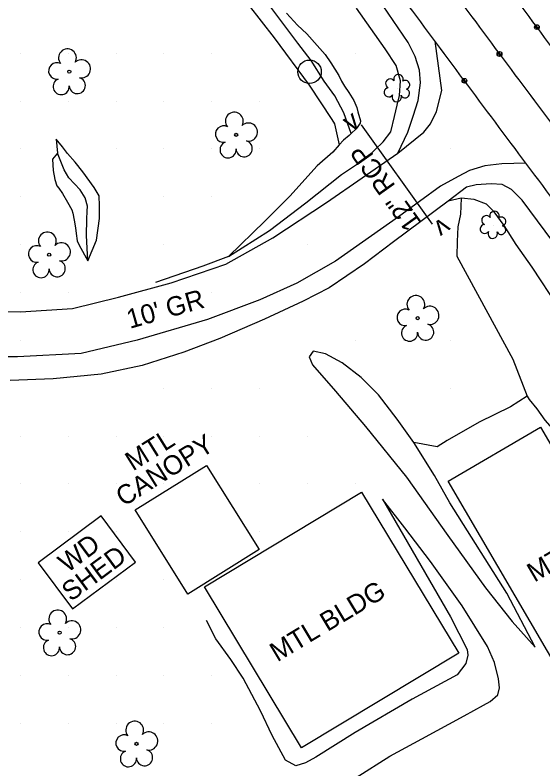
# Model space of a CAD drawing. Extents: x 1548934 to 1561348, y 809680 to 824075.
# Drawn here: x 1552078.9 to 1552189.3, y 809960.4 to 810117.9 of the extents above; entities that cross this region are included whole.
import ezdxf

# ---------------------------------------------------------------- set-up
doc = ezdxf.new("R2010")
doc.units = 0
for name, color, linetype in [('Default', 7, 'Continuous'), ('E_NCDOT_Vertical_Profile_Ground_Line', 7, 'Continuous'), ('Exist Building', 7, 'Continuous'), ('Exist Building Foundations Text', 7, 'Continuous'), ('Exist Building Metal Canopy', 7, 'Continuous'), ('Exist Building Metal Canopy Text', 7, 'Continuous'), ('Exist DTM QL2 LIDAR Elevation Point', 7, 'Continuous'), ('Exist Roads Soil', 7, 'Continuous'), ('Exist Roads Soil Text', 7, 'Continuous'), ('Exist Structure Minor Culvert Topo', 7, 'Continuous'), ('Exist Structure Minor Culvert Topo Terminator', 7, 'Continuous'), ('Exist Structure Minor Pipes RCP 12 Inch Text', 7, 'Continuous'), ('Exist Utilities Other Pole CELL', 7, 'Continuous'), ('Exist Vegetation Shrub CELL', 7, 'Continuous'), ('Exist Vegetation Tree CELL', 7, 'Continuous'), ('P_NCDOT_Vertical_Profile_Grade_Minor_Road', 7, 'Continuous'), ('PH Exist DTM Breakline', 7, 'Continuous')]:
    doc.layers.add(name, color=color, linetype=linetype)

# ---------------------------------------------------------------- blocks, each defined once
blk = doc.blocks.new('SurveyPointCell')
at = {"layer": 'Default'}
for p, q in [((-0.5, 0), (0.5, 0)), ((0, -0.5), (0, 0.5))]:
    blk.add_line(p, q, dxfattribs=at)
blk.add_circle((0, 0), 0.5, dxfattribs=at)

msp = doc.modelspace()

# ---------------------------------------------------------------- linework, layer by layer
at = {"layer": 'E_NCDOT_Vertical_Profile_Ground_Line'}
for points in [[(1552269.12, 810011.85), (1552259.92, 810023.16), (1552240.77, 810045.39), (1552214.34, 810080.42), (1552187.87, 810115.32), (1552162.13, 810150.99), (1552135.64, 810187.58), (1552109.72, 810225.45), (1552084.15, 810264.06), (1552058.91, 810303.06), (1552035.06, 810342.6), (1552011.64, 810381.93), (1551989.04, 810421.64), (1551966.75, 810462.54), (1551944.7, 810504.81), (1551922.38, 810547.42), (1551904.22, 810585.98), (1551891.94, 810609.51), (1551888.01, 810619.12)], [(1552253.41, 809998.89), (1552244.07, 810010.35), (1552226, 810034.01), (1552199.08, 810069.05), (1552172.73, 810104.35), (1552146.5, 810139.67), (1552120.17, 810176.34), (1552094.24, 810214.53), (1552068.08, 810253.47), (1552042.84, 810293.18), (1552018.16, 810332.72), (1551995.31, 810372.57), (1551972.35, 810412.52), (1551950.07, 810453.78), (1551927.46, 810496.24), (1551905.62, 810539.48), (1551886.94, 810576.33), (1551876.35, 810599.17), (1551872.14, 810607.03)]]:
    msp.add_open_spline(points, degree=3, dxfattribs=at)
at = {"layer": 'Exist Building'}
for points in [[(1552200.63, 809967.19), (1552169.44, 810020.48), (1552188.74, 810031.78), (1552219.93, 809978.48)], [(1552151.36, 810018.23), (1552171.66, 809984.55), (1552138.81, 809964.75), (1552118.5, 809998.42)], [(1552104.08, 810003.58), (1552096.93, 810013.24), (1552083.72, 810003.45), (1552090.88, 809993.8)]]:
    msp.add_lwpolyline(points, close=True, dxfattribs=at)
at = {"layer": 'Exist Building Metal Canopy'}
msp.add_lwpolyline([(1552115.03, 809996.9), (1552104.01, 810014.49), (1552118.9, 810023.82), (1552129.92, 810006.23)], close=True, dxfattribs=at)
at = {"layer": 'Exist DTM QL2 LIDAR Elevation Point'}
for p, q in [((1552080.03, 810109.94), (1552080.03, 810109.94)), ((1552090.03, 810109.94), (1552090.03, 810109.94)), ((1552100.03, 810109.94), (1552100.03, 810109.94)), ((1552110.03, 810109.94), (1552110.03, 810109.94)), ((1552120.03, 810109.94), (1552120.03, 810109.94)), ((1552150.03, 810109.94), (1552150.03, 810109.94)), ((1552080.03, 810099.94), (1552080.03, 810099.94)), ((1552090.03, 810099.94), (1552090.03, 810099.94)), ((1552100.03, 810099.94), (1552100.03, 810099.94)), ((1552110.03, 810099.94), (1552110.03, 810099.94)), ((1552120.03, 810099.94), (1552120.03, 810099.94)), ((1552130.03, 810099.94), (1552130.03, 810099.94)), ((1552080.03, 810089.94), (1552080.03, 810089.94)), ((1552100.03, 810089.94), (1552100.03, 810089.94)), ((1552110.03, 810089.94), (1552110.03, 810089.94)), ((1552120.03, 810089.94), (1552120.03, 810089.94)), ((1552130.03, 810089.94), (1552130.03, 810089.94)), ((1552170.03, 810089.94), (1552170.03, 810089.94)), ((1552080.03, 810079.94), (1552080.03, 810079.94)), ((1552110.03, 810079.94), (1552110.03, 810079.94)), ((1552120.03, 810079.94), (1552120.03, 810079.94)), ((1552080.03, 810069.94), (1552080.03, 810069.94)), ((1552110.03, 810069.94), (1552110.03, 810069.94)), ((1552140.03, 810069.94), (1552140.03, 810069.94)), ((1552080.03, 810059.94), (1552080.03, 810059.94)), ((1552090.03, 810059.94), (1552090.03, 810059.94)), ((1552120.03, 810059.94), (1552120.03, 810059.94)), ((1552080.03, 810049.94), (1552080.03, 810049.94)), ((1552150.03, 810049.94), (1552150.03, 810049.94)), ((1552160.03, 810049.94), (1552160.03, 810049.94)), ((1552170.03, 810049.94), (1552170.03, 810049.94)), ((1552110.03, 810039.93), (1552110.03, 810039.93)), ((1552120.03, 810039.93), (1552120.03, 810039.93)), ((1552130.03, 810039.93), (1552130.03, 810039.93)), ((1552170.03, 810039.93), (1552170.03, 810039.93)), ((1552080.03, 810029.93), (1552080.03, 810029.93)), ((1552090.03, 810029.93), (1552090.03, 810029.93)), ((1552100.03, 810029.93), (1552100.03, 810029.93)), ((1552110.03, 810029.93), (1552110.03, 810029.93)), ((1552120.03, 810029.93), (1552120.03, 810029.93)), ((1552130.03, 810029.93), (1552130.03, 810029.93)), ((1552140.03, 810029.93), (1552140.03, 810029.93)), ((1552080.03, 810019.93), (1552080.03, 810019.93)), ((1552090.03, 810019.93), (1552090.03, 810019.93)), ((1552100.03, 810019.93), (1552100.03, 810019.93)), ((1552110.03, 810019.93), (1552110.03, 810019.93)), ((1552130.03, 810019.93), (1552130.03, 810019.93)), ((1552140.03, 810019.93), (1552140.03, 810019.93)), ((1552150.03, 810019.93), (1552150.03, 810019.93)), ((1552080.03, 810009.93), (1552080.03, 810009.93)), ((1552090.03, 810009.93), (1552090.03, 810009.93)), ((1552100.03, 810009.93), (1552100.03, 810009.93)), ((1552130.03, 810009.93), (1552130.03, 810009.93)), ((1552080.03, 809999.93), (1552080.03, 809999.93)), ((1552100.03, 809999.93), (1552100.03, 809999.93)), ((1552110.03, 809999.93), (1552110.03, 809999.93)), ((1552120.03, 809999.93), (1552120.03, 809999.93)), ((1552080.03, 809989.93), (1552080.03, 809989.93)), ((1552090.03, 809989.93), (1552090.03, 809989.93)), ((1552100.03, 809989.93), (1552100.03, 809989.93)), ((1552110.03, 809989.93), (1552110.03, 809989.93)), ((1552080.03, 809979.93), (1552080.03, 809979.93)), ((1552090.03, 809979.93), (1552090.03, 809979.93)), ((1552100.03, 809979.93), (1552100.03, 809979.93)), ((1552110.03, 809979.93), (1552110.03, 809979.93)), ((1552120.03, 809979.93), (1552120.03, 809979.93)), ((1552080.03, 809969.93), (1552080.03, 809969.93)), ((1552090.03, 809969.93), (1552090.03, 809969.93)), ((1552100.03, 809969.93), (1552100.03, 809969.93)), ((1552110.03, 809969.93), (1552110.03, 809969.93)), ((1552120.03, 809969.93), (1552120.03, 809969.93))]:
    msp.add_line(p, q, dxfattribs=at)
at = {"layer": 'Exist Roads Soil'}
for points in [[(1552044.96, 810063.14), (1552052.35, 810059.76), (1552062.2, 810057.09), (1552070.88, 810056.03), (1552080.06, 810055.92), (1552090.93, 810056.58), (1552100.5, 810058.98), (1552111.54, 810061.99), (1552122.94, 810065.88), (1552132.77, 810071.34), (1552144.02, 810078.74), (1552158.97, 810089.08), (1552164.36, 810093.46), (1552165.76, 810095.23), (1552167.04, 810097.8), (1552168.11, 810102.17), (1552166.72, 810112.47)], [(1552185.73, 810086.96), (1552180.66, 810086.85), (1552177.16, 810086.45), (1552173.95, 810085.47), (1552171.53, 810084.19), (1552167.84, 810082.19), (1552159.11, 810075.77), (1552145.91, 810066.49), (1552137.8, 810061.9), (1552130.07, 810058.38), (1552119.16, 810054.32), (1552104.43, 810049.99), (1552092.73, 810047.17), (1552079.42, 810046.49), (1552071.79, 810046.48), (1552062.54, 810047.25), (1552052.29, 810048.42), (1552044.39, 810051.11), (1552038.17, 810053.8), (1552035.61, 810056.33)]]:
    msp.add_lwpolyline(points, dxfattribs=at)
at = {"layer": 'Exist Structure Minor Culvert Topo'}
msp.add_line((1552151.26, 810095.02), (1552166.12, 810074.23), dxfattribs=at)
at = {"layer": 'Exist Utilities Other Pole CELL'}
msp.add_circle((1552140.48, 810106.08), 2.46, dxfattribs=at)
at = {"layer": 'Exist Vegetation Shrub CELL'}
for p, q in [((1552158.83, 810102.49), (1552158.83, 810102.49)), ((1552178.91, 810073.92), (1552178.91, 810073.92))]:
    msp.add_line(p, q, dxfattribs=at)
for centre, radius, start, end in [((1552159.06, 810104.53), 0.99, 334.8391, 200.4717), ((1552157.35, 810103.61), 0.968, 35.8908, 245.4216), ((1552160.5, 810103.36), 0.929, 284.4567, 126.0861), ((1552157.03, 810101.78), 0.955, 95.1099, 327.9534), ((1552160.47, 810101.56), 0.937, 204.9913, 73.4601), ((1552158.7, 810100.8), 0.984, 151.2797, 21.387), ((1552179.14, 810075.96), 0.99, 334.8391, 200.4717), ((1552177.43, 810075.05), 0.968, 35.8908, 245.4216), ((1552180.58, 810074.79), 0.929, 284.4567, 126.0861), ((1552177.11, 810073.22), 0.955, 95.1099, 327.9534), ((1552180.55, 810073), 0.937, 204.9913, 73.4601), ((1552178.78, 810072.24), 0.984, 151.2797, 21.387)]:
    msp.add_arc(centre, radius, start, end, dxfattribs=at)
at = {"layer": 'Exist Vegetation Tree CELL'}
for p, q in [((1552090.25, 810106.11), (1552090.25, 810106.11)), ((1552125.14, 810092.89), (1552125.14, 810092.89)), ((1552086.04, 810067.84), (1552086.04, 810067.84)), ((1552163.09, 810054.58), (1552163.09, 810054.58)), ((1552088.21, 809988.84), (1552088.21, 809988.84)), ((1552104.3, 809965.62), (1552104.3, 809965.62))]:
    msp.add_line(p, q, dxfattribs=at)
for centre in [(1552090.25, 810106.11), (1552125.14, 810092.89), (1552086.04, 810067.84), (1552163.09, 810054.58), (1552088.21, 809988.84), (1552104.3, 809965.62)]:
    msp.add_circle(centre, 0.326, dxfattribs=at)
for centre, radius, start, end in [((1552089.86, 810108.99), 1.86, 330.1651, 219.7134), ((1552092.79, 810106.7), 1.9, 257.1011, 134.1999), ((1552087.64, 810106.27), 1.73, 62.6636, 279.3457), ((1552088.54, 810102.99), 1.69, 111.5671, 6.231), ((1552091.92, 810103.21), 1.7, 181.2822, 74.56), ((1552124.75, 810095.77), 1.86, 330.1651, 219.7134), ((1552122.53, 810093.05), 1.73, 62.6636, 279.3457), ((1552127.69, 810093.48), 1.9, 257.1011, 134.1999), ((1552123.44, 810089.77), 1.69, 111.5671, 6.231), ((1552126.81, 810090), 1.7, 181.2822, 74.56), ((1552085.65, 810070.72), 1.86, 330.1651, 219.7134), ((1552083.43, 810068), 1.73, 62.6636, 279.3457), ((1552088.59, 810068.43), 1.9, 257.1011, 134.1999), ((1552084.33, 810064.72), 1.69, 111.5671, 6.231), ((1552087.71, 810064.94), 1.7, 181.2822, 74.56), ((1552162.71, 810057.45), 1.86, 330.1651, 219.7134), ((1552165.64, 810055.17), 1.9, 257.1011, 134.1999), ((1552160.49, 810054.73), 1.73, 62.6636, 279.3457), ((1552161.39, 810051.46), 1.69, 111.5671, 6.231), ((1552164.76, 810051.68), 1.7, 181.2822, 74.56), ((1552087.83, 809991.71), 1.86, 330.1651, 219.7134), ((1552085.6, 809988.99), 1.73, 62.6636, 279.3457), ((1552090.76, 809989.43), 1.9, 257.1011, 134.1999), ((1552086.51, 809985.72), 1.69, 111.5671, 6.231), ((1552089.88, 809985.94), 1.7, 181.2822, 74.56), ((1552103.92, 809968.49), 1.86, 330.1651, 219.7134), ((1552101.7, 809965.77), 1.73, 62.6636, 279.3457), ((1552106.85, 809966.2), 1.9, 257.1011, 134.1999), ((1552102.6, 809962.5), 1.69, 111.5671, 6.231), ((1552105.97, 809962.72), 1.7, 181.2822, 74.56)]:
    msp.add_arc(centre, radius, start, end, dxfattribs=at)
at = {"layer": 'P_NCDOT_Vertical_Profile_Grade_Minor_Road'}
msp.add_open_spline([(1551879.82, 810614.21), (1551884.04, 810605.38), (1551895.16, 810581.81), (1551913.82, 810543.91), (1551935.87, 810500.72), (1551958.31, 810458.4), (1551980.95, 810417.47), (1552003.45, 810377.53), (1552026.54, 810337.94), (1552050.88, 810298.39), (1552075.93, 810258.79), (1552101.83, 810219.9), (1552127.9, 810181.92), (1552154.01, 810145.19), (1552180.07, 810109.84), (1552206.52, 810074.71), (1552233.37, 810039.85), (1552251.61, 810016.53), (1552260.84, 810005.28)], degree=3, dxfattribs=at)
at = {"layer": 'PH Exist DTM Breakline'}
for points in [[(1552031.09, 810258.86), (1552034.12, 810253.01), (1552038.46, 810246.99), (1552043.38, 810240.62), (1552053.3, 810226.91), (1552065.13, 810210.65), (1552072.2, 810200.07), (1552080.28, 810187.2), (1552089.43, 810173.57), (1552098.48, 810160.06), (1552107.27, 810147.29), (1552115.52, 810136.18), (1552124.92, 810123.69), (1552133.11, 810113.15), (1552140.37, 810103.29), (1552145.12, 810096.11), (1552145.71, 810095.17), (1552146.69, 810090.84)], [(1552158.97, 810089.08), (1552161.06, 810093.49), (1552162.17, 810096.81), (1552163.17, 810100.05), (1552163.66, 810103.74), (1552163.44, 810106.4), (1552162.57, 810109.26), (1552161.08, 810112.2), (1552154.8, 810121.44), (1552141.96, 810139.91), (1552132.34, 810153.32), (1552120.52, 810170.3), (1552111.12, 810183.22), (1552101.94, 810196.1), (1552094.74, 810206.28), (1552087.72, 810216.38), (1552077.67, 810231.11)], [(1552149.19, 810093.18), (1552147.66, 810097.47), (1552145.78, 810101.08), (1552143.54, 810104.12), (1552140.85, 810108.45), (1552138.03, 810112.03), (1552133.85, 810117.61), (1552129.49, 810123.53), (1552125.94, 810128.89), (1552122.04, 810134.63), (1552114.71, 810144.42), (1552109.77, 810151.43), (1552104.51, 810158.52), (1552098.53, 810166.75), (1552089.43, 810180.1), (1552083.79, 810188.91), (1552077.39, 810199.33)], [(1552135.64, 810118.33), (1552137.94, 810115.81), (1552139.92, 810114.04), (1552142.04, 810111.57), (1552143.73, 810109.7), (1552144.95, 810107.93), (1552146.6, 810105.28), (1552147.18, 810104.09), (1552147.81, 810103.08), (1552148.71, 810101.78), (1552149.75, 810100.06), (1552150.33, 810098.59), (1552150.59, 810097.72), (1552151.16, 810095.82), (1552151.07, 810095.31), (1552150.25, 810094.15), (1552149.19, 810093.18), (1552148.75, 810092.76), (1552147.59, 810091.8), (1552146.69, 810090.84), (1552145.36, 810089.29), (1552142.07, 810086.44), (1552136.38, 810080.05), (1552131.14, 810074.84), (1552123.53, 810067.5), (1552118.19, 810065.43), (1552108.3, 810062.07)], [(1552123.53, 810067.5), (1552132.11, 810072.88), (1552139.73, 810078.67), (1552147.13, 810084.64), (1552152.41, 810088.09), (1552155.85, 810091.41), (1552157.46, 810093.55), (1552158.21, 810096.72), (1552158.77, 810099.08), (1552159.29, 810101.09), (1552159.46, 810104.22), (1552158.59, 810107.41), (1552156.32, 810110.91), (1552150.29, 810119.36)], [(1552094.11, 810066.54), (1552095.95, 810070.89), (1552096.54, 810075.38), (1552096.57, 810078.09), (1552096.48, 810080.15), (1552095.47, 810081.88), (1552093.04, 810085.2), (1552091.48, 810087.18), (1552089.88, 810089.01), (1552088.83, 810090.42), (1552087.47, 810091.99), (1552087.76, 810089.1)], [(1552093.85, 810071.88), (1552093.88, 810075.28), (1552094, 810076.92), (1552094.02, 810077.97), (1552093.54, 810079.74), (1552092.49, 810081.42), (1552090.15, 810083.92), (1552089.17, 810085.56), (1552087.76, 810089.1), (1552086.76, 810087.84), (1552086.85, 810085.48), (1552087.19, 810083.56), (1552087.62, 810082.22), (1552088.05, 810081.72), (1552088.84, 810080.61), (1552089.87, 810078.84), (1552090.75, 810077.21), (1552091.01, 810076.5), (1552091.27, 810075.05), (1552091.54, 810073.45), (1552091.66, 810072.3), (1552091.91, 810070.74), (1552092.29, 810069.83), (1552094.11, 810066.54), (1552093.85, 810071.88)], [(1552356.24, 809868), (1552340.53, 809884.63), (1552327.84, 809898.55), (1552316.59, 809912.56), (1552306.45, 809924.02), (1552292.89, 809939.25), (1552277.3, 809956.75), (1552264.65, 809972.75), (1552251.75, 809990.37), (1552225.73, 810024.02), (1552209.75, 810045.24), (1552199.26, 810059.94), (1552191.33, 810070.6), (1552184.93, 810079.24), (1552182.73, 810081.48), (1552180.73, 810082.53), (1552178.46, 810082.68), (1552175.3, 810082.44), (1552173.27, 810081.94), (1552169.49, 810079.05)], [(1552192.51, 810056.86), (1552187.02, 810065.24), (1552183.66, 810069.99), (1552181.14, 810073.95), (1552179.11, 810076.78), (1552177.47, 810078.38), (1552174.9, 810079.35), (1552172.17, 810079.64), (1552169.49, 810079.05), (1552158.03, 810070.55), (1552151.95, 810065.92), (1552144.56, 810060.95), (1552139.12, 810058.15), (1552131.07, 810054.37), (1552121.74, 810050.33), (1552114.16, 810047.49), (1552105.49, 810044.66), (1552096.89, 810042.89), (1552086.84, 810041.89), (1552077.9, 810041.58)], [(1552172.17, 810079.64), (1552172.02, 810076.34), (1552171.5, 810073.65), (1552171.32, 810070.64), (1552171.26, 810067.51), (1552175.62, 810059.63), (1552182.98, 810046.03), (1552185.98, 810038.25), (1552186.43, 810037.6), (1552188.01, 810035.65), (1552189.66, 810033.29), (1552197.66, 810024.12), (1552205.38, 810011.98), (1552215.83, 809993.87), (1552221.18, 809984.65), (1552223.03, 809982.36), (1552225.15, 809979.94), (1552231.97, 809970.94), (1552239.31, 809962.57), (1552249.67, 809951.73)], [(1552181.7, 809997.11), (1552169.81, 810015.96), (1552166.59, 810021.67), (1552162.27, 810028.61), (1552158.77, 810033.48), (1552154.88, 810038.58), (1552151.24, 810042.15), (1552147.33, 810045.26), (1552143.78, 810047.16), (1552141.24, 810047.66), (1552140.41, 810046.48), (1552141.08, 810044.8), (1552145.92, 810039.3), (1552152.16, 810031.93), (1552160.73, 810021.35), (1552169.36, 810009.16), (1552177.24, 809998.25), (1552182.86, 809991.18), (1552187.65, 809985.81), (1552181.7, 809997.11)], [(1552185.98, 810038.25), (1552182.51, 810036.05), (1552175.94, 810032.87), (1552169.25, 810028.99), (1552167.19, 810027.72), (1552162.27, 810028.61)], [(1552150.23, 809958.59), (1552157.28, 809963.02), (1552163.95, 809966.66), (1552172.79, 809971.44), (1552176.85, 809973.7), (1552178.26, 809974.49), (1552179.84, 809975.87), (1552180.2, 809977.33), (1552179.99, 809979.17), (1552179.13, 809982.62), (1552177.65, 809985.93), (1552172.39, 809994.45), (1552165.76, 810003.74), (1552160.39, 810010.75), (1552155.73, 810016.76), (1552169.96, 809992.18), (1552173.44, 809985.31), (1552173.56, 809984.17), (1552173.15, 809982.41), (1552171.36, 809980), (1552161.95, 809974.94), (1552149.99, 809967.95), (1552141.79, 809962.81), (1552139.62, 809961.66), (1552137.63, 809961.03), (1552135.45, 809962.17), (1552132.64, 809967.36), (1552130.2, 809972.54), (1552126.59, 809979.37), (1552124.03, 809983.24), (1552120.86, 809987.57), (1552118.91, 809991.38)]]:
    msp.add_lwpolyline(points, dxfattribs=at)

# ---------------------------------------------------------------- block references
at = {"layer": 'Default'}
for p in [(1552188.01, 810115.42), (1552180.19, 810109.8), (1552172.86, 810104.21)]:
    msp.add_blockref('SurveyPointCell', p, dxfattribs=at)

# ---------------------------------------------------------------- texts
at = {"layer": 'Exist Building Foundations Text'}
for s, rotation, p in [('WD', 36.6143, (1552089.85, 810001.23)), ('SHED', 36.5469, (1552090.57, 809995.23)), ('MTL', 30.3379, (1552187.48, 809999.29)), ('MTL BLDG', 31.0849, (1552133.74, 809982.64))]:
    msp.add_text(s, height=4.02, rotation=rotation, dxfattribs=at).set_placement(p)
at = {"layer": 'Exist Building Metal Canopy Text'}
for s, p in [('CANOPY', (1552101.6, 810015.1)), ('MTL', (1552103.56, 810022.53))]:
    msp.add_text(s, height=4.02, rotation=32.0625, dxfattribs=at).set_placement(p)
at = {"layer": 'Exist Roads Soil Text'}
msp.add_text("10' GR", height=4.02, rotation=15.847, dxfattribs=at).set_placement((1552102.9, 810052.34))
at = {"layer": 'Exist Structure Minor Culvert Topo Terminator'}
for rotation, p in [(35.545, (1552149.11, 810093.48)), (215.545, (1552168.27, 810075.77))]:
    msp.add_text('v', height=4, rotation=rotation, dxfattribs=at).set_placement(p)
at = {"layer": 'Exist Structure Minor Pipes RCP 12 Inch Text'}
msp.add_text('12" RCP', height=4.02, rotation=125.545, dxfattribs=at).set_placement((1552164.02, 810074.58))

doc.saveas('drawing.dxf')
